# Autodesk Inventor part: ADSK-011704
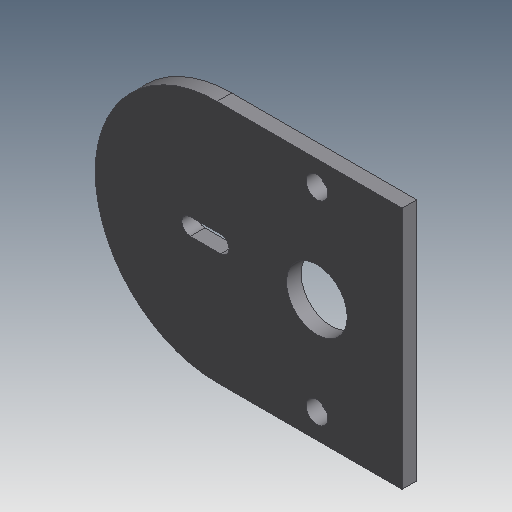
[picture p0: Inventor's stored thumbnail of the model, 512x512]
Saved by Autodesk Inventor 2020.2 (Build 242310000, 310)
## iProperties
Created: 2000-03
Part Number: ADSK-011704
Material: Pearson HRS
Document SubType Name: Modeling
Designer: sspink
Density: 7.83 g/cm^3
Appearance: Métal - Acier
Mass: 506.581 g
Surface Area: 251.128 cm^2
Volume: 64.6974 cm^3
Control State: 0
Master: False
Checked Out: False
Shininess: 0.0
Length Units: 11269
Angle Units: 11279
Time Units: 11290
Mass Units: 11283
Length Display Precision: 3
Angle Display Precision: 2
Compacted: True
Cutlength: 5.06
Material Desc: FLAT,HRS,0.250X04.000
Material_Number: A084338
Dimensions: 100x6x126 mm
Mass: 0,507 kg
VLT_Material: Pearson HRS
Density: 0.0
Volumn: 0.0
Area: 0.0
PropertySet Name: Model Information
Author: sspink
Revision Number: -
Title: ADSK-011704
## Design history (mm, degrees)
node "Solide1"
  node "Extrusion1" dims "d8" = 6, "d9" = 0
  node "Hole1" dims "d15" = 9, "d16" = 9.525, "d17" = 6.35, "d18" = 60 deg, "d19" = 19.05, "d20" = 118 deg, "d28" = 6
  node "Extrusion2" dims "d25" = 6.35, "d26" = 0
sketch "Sketch1"
  geometry: L1 (-41, -50)-(35, -50); L2 (35, -50)-(35, 50); L3 (35, 50)-(-41, 50); L4 (-41, 50)-(-41, -50); C1 r 12.5 at (0, 0); A1 r 50 centre (-41, 0) between (-41, 50) and (-41, -50); 5 further points
  constraints: 8 end point, 4 midpoint, 2 centre point, 2 coincident, 2 parallel, 2 point on circle, 1 horizontal, 1 horizontal alignment, 1 perpendicular
  dimensions: "d0" = 76 distance between parallel lines of L2 L4; "d7" = 100 distance between parallel lines of L1 L3; "d10" = 25 diameter of C1; "d30" = 35 distance from line of C1.centre L2
sketch "Sketch2"
  geometry: L1 (0, 40)-(0, -40); C1 r 12.5 at (0, 0) reference; 1 further point
  constraints: 2 end point, 1 coincident, 1 midpoint, 1 vertical
  dimensions: "d27" = 80 distance of L1.start L1.end
sketch "Sketch3"
  geometry: L1 (-35, -50)-(-35, 50) reference; L2 (39.5, 3.5)-(52, 3.5); L3 (52, 3.5)-(52, -3.5); L4 (52, -3.5)-(39.5, -3.5); L5 (39.5, -3.5)-(39.5, 3.5); A1 r 3.5 centre (52, 0) between (52, -3.5) and (52, 3.5); A2 r 3.5 centre (39.5, 0) between (39.5, 3.5) and (39.5, -3.5); 1 further point
  constraints: 8 end point, 4 point on circle, 2 centre point, 2 parallel, 2 tangent, 1 horizontal, 1 horizontal alignment, 1 midpoint, 1 perpendicular
  dimensions: "d21" = 7 distance between parallel lines of L2 L4; "d22" = 12.5 distance of L3.end L4.end; "d24" = 74.5 distance from line of A2.centre L1
workaxis "Arbeitsachse1"
workplane "Arbeitsebene1"
node "Corps solides"
node "Corps surfaciques"
other parameters: "d29" = 90 deg
